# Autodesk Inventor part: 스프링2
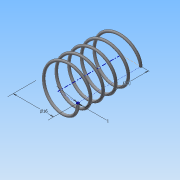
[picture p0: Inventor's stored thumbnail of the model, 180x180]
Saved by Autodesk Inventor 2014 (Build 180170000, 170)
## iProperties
Created: 2015-06
Part Number: 스프링2
Material: 강철, 연강
Document SubType Name: Modeling
Designer: Administrator
Density: 7.86 g/cm^3
Appearance: 강철
Mass: 1.53479 g
Surface Area: 7.89194 cm^2
Volume: 0.195266 cm^3
Author: Administrator
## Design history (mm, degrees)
sketch "스케치1"
  geometry: L1 (0, 0)-(8, 0); L2 (8, 0)-(8, 21.5); L3 (8, 21.5)-(0, 21.5); L4 (0, 21.5)-(0, 0); C1 r 0.5 at (8, 0)
  constraints: 8 end point, 2 parallel, 1 centre point, 1 coincident, 1 horizontal, 1 perpendicular
  dimensions: "d0" = 16 diameter of L2 L4; "d1" = 21.5 distance of L1.end L2.end (derived); "d2" = 1 diameter of C1
feature "코일1" sketch "스케치1" pitch "d3" = 10; turns "d5" = 5; dims "d4" = 21.5 (= d1), "d6" = 0, angle "d7" = 90 deg, angle "d8" = 90 deg, "d9" = 0, "d10" = 0
node "작업 평면1"
sketch "스케치2"
  geometry: L1 (-8.5, 0)-(-7.5, 0) reference; 1 further point
  constraints: 1 horizontal alignment
extrude "돌출1" cut sketch "스케치2" stored distance "d12" = 10; taper "d13" = 0 deg
node "작업 평면2"
sketch "스케치3"
  geometry: L1 (-7.5, 0)-(-8.5, 0) reference; 1 further point
  constraints: 1 horizontal alignment
extrude "돌출2" cut sketch "스케치3" stored distance "d15" = 10; taper "d16" = 0 deg
node "솔리드1"
node "절단 모서리 투영1"
node "절단 모서리 투영2"
other parameters: "d11" = 0, "d14" = 21.5 (= d1)
